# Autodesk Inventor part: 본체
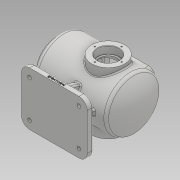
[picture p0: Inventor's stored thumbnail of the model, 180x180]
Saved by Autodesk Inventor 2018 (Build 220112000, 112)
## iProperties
Created: 2021-11
Part Number: 본체
Material: 일반
Document SubType Name: Modeling
Designer: home
Density: 1 g/cm^3
Appearance: 기본값
Author: home
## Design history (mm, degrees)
sketch "스케치1"
  geometry: L1 (-105, 32.5)-(-105, 47.5); L2 (-105, 47.5)-(-95, 47.5); L3 (-95, 47.5)-(-95, 65); L4 (-95, 65)-(80.993, 65); L5 (-105, 0)-(105, 0); L6 (-105, 32.5)-(-80, 32.5); L7 (-80, 32.5)-(-80, 55); L8 (-80, 55)-(76.239, 55); L9 (95, 0)-(105, 0); A1 r 100 centre (5, 0) between (105, 0) and (80.993, 65); A2 r 90 centre (5, 0) between (95, 0) and (76.239, 55); 2 further points
  constraints: 18 end point, 4 perpendicular, 4 point on circle, 3 vertical, 2 centre point, 2 coincident, 2 horizontal, 1 tangent
  dimensions: "d0" = 210 distance of L5.start L5.end; "d1" = 47.5 distance of L5.start L1.end; "d2" = 10 distance of L1.end L2.end; "d3" = 17.5 distance of L2.end L3.end; "d8" = 10 distance of L9.start L5.end; "d9" = 90 distance of L9.start A1.centre; "d11" = 32.5 distance of L1.start L5.start; "d12" = 25 distance of L1.start L6.end; "d13" = 22.5 distance of L6.end L7.end; "d14" = 65 diameter of L6 L5; "d15" = 95 diameter of L2 L5 (derived); "d16" = 110 diameter of L8 L5 (derived); "d17" = 130 diameter of L4 L5 (derived); "d18" = 0 distance from line of point (0, 0) L9; "d19" = 80 distance from line of point (0, 0) L7
revolve "회전1" sketch "스케치1" stored, may be unused: angle "d20" = 90 deg
node "작업 평면1"
sketch "스케치2"
  geometry: L1 (0, 0)-(0, -114); L2 (0, -114)-(-65, -114); L3 (0, -114)-(65, -114); L4 (-65, -114)-(-65, -100); L5 (-65, -100)-(65, -100); L6 (65, -100)-(65, -114)
  constraints: 12 end point, 2 vertical, 1 horizontal, 1 perpendicular, 1 point on line
  dimensions: "d22" = 114 distance of L1.start L1.end; "d23" = 65 distance of L1.end L2.end; "d24" = 65 distance of L1.end L3.end; "d25" = 14 distance of L2.end L4.end; "d26" = 130 distance of L4.end L5.end
extrude "돌출1" join sketch "스케치2" distance "d27" = 160; taper "d28" = 0 deg
node "작업 평면2"
sketch "스케치6"
  geometry: L1 (-105, -47.5)-(-105, 47.5) reference; C1 r 40 at (22, 0); 1 further point
  constraints: 1 centre point
  dimensions: "d61" = 80 diameter of C1; "d62" = 127 distance from line of C1.centre L1; "d63" = 22 distance of C1.centre point (0, 0)
extrude "돌출3" join sketch "스케치6" stored distance "d64" = 160; taper "d65" = 0 deg
sketch "스케치7"
  geometry: C1 r 40 at (0, 0) reference; C2 r 26 at (0, 0); 1 further point
  constraints: 1 centre point, 1 coincident
  dimensions: "d66" = 52 diameter of C2
extrude "돌출4" cut sketch "스케치7" distance "d67" = 18; taper "d68" = 0 deg
sketch "스케치8"
  geometry: C1 r 26 at (0, 0) reference; C2 r 21 at (0, 0); 1 further point
  constraints: 1 centre point, 1 coincident
  dimensions: "d69" = 42 diameter of C2
extrude "돌출5" cut sketch "스케치8" extent not by distance; stored distance "d70" = 18; taper "d71" = 0 deg
node "작업 평면3"
sketch "스케치9"
  geometry: L1 (105, 47.5)-(105, -47.5) reference; L2 (55, 0)-(55, -30); L3 (55, -30)-(-65, -30); L4 (-65, -30)-(-65, 30); L5 (-65, 30)-(55, 30); L6 (55, 30)-(55, 0); 1 further point
  constraints: 10 end point, 2 perpendicular, 1 parallel, 1 point on line
  dimensions: "d74" = 30 distance of L2.start L2.end; "d75" = 120 distance of L2.end L3.end; "d76" = 60 distance of L3.end L4.end; "d77" = 120 distance of L4.end L5.end; "d78" = 50 distance between parallel lines of L2 L1; "d79" = 17.5 distance from line of L1.start L5
extrude "돌출6" join sketch "스케치9" stored distance "d80" = 18; taper "d81" = 0 deg
sketch "스케치11"
  geometry: L1 (-55, 30)-(65, 30) reference; L2 (65, -30)-(-55, -30) reference; L3 (-50, 0)-(60, 0); L4 (-64, 156)-(-64, 106); L5 (5, 0)-(5, 25); L6 (5, 0)-(5, -25); 5 further points
  constraints: 8 end point, 4 coincident, 2 vertical, 1 horizontal, 1 midpoint, 1 point on line
  dimensions: "d93" = 110 distance of L3.start L3.end; "d94" = 50 distance of L4.start L4.end; "d96" = 25 distance of L5.start L5.end; "d97" = 25 distance of L5.start L6.end; "d98" = 30 distance between parallel lines of L2 L3; "d99" = 69 distance between parallel lines of L6 L4; "d100" = 60 distance from line of L1.end L6; "d101" = 186 distance from line of L4.start L2
hole "구멍1" sketch "스케치11" at (5, 25), (60, 0), (5, -25), (-50, 0) diameter "d102" = 3.242; stored, may be unused: countersink angle "d106" = 90 deg, drill point angle "d108" = 118 deg; dims "d103" = 9, "d104" = 4, "d105" = 2, "d107" = 11
sketch "스케치12" dims "d109" = 65
  geometry: C1 r 21 at (0, 0) reference; 6 further points
  constraints: 1 coincident, 1 vertical alignment, 2 other
  dimensions: "d113" = 54.5 distance of point (-22, 0) point (32.5, 0); "d114" = 39.24602 distance of point (-22, 0) point (0, 32.5); "d115" = 39.24602 distance of point (-22, 0) point (0, -32.5); "d116" = 10.5 distance of point (-22, 0) point (-32.5, 0); "d117" = 32.5 distance of point (32.5, 0) C1.centre; "d118" = 32.5 distance of point (0, -32.5) C1.centre; "d119" = 32.5 distance of point (-32.5, 0) C1.centre
hole "구멍2" sketch "스케치12" at (0, 32.5), (-32.5, 0), (0, -32.5), (32.5, 0) diameter "d120" = 3.242; stored, may be unused: countersink angle "d124" = 90 deg, drill point angle "d126" = 118 deg; dims "d121" = 11, "d122" = 4, "d123" = 2, "d125" = 13
sketch "스케치13" dims "d127" = 80
  geometry: 6 further points
  constraints: 1 coincident, 1 vertical alignment, 7 other
  dimensions: "d130" = 360 deg dimension on point (0, 0) point (0, 40) (derived)
hole "구멍3" sketch "스케치13" at (0, 40), (-40, 0), (0, -40), (40, 0) diameter "d132" = 3.242; stored, may be unused: countersink angle "d136" = 90 deg, drill point angle "d138" = 118 deg; dims "d133" = 11, "d134" = 4, "d135" = 2, "d137" = 13
fillet "모깎기1" dims "d139" = 20
fillet "모깎기2" dims "d146" = 10
chamfer "모따기1" distance "d147" = 1; stored, may be unused: second distance "d148" = 2, angle "d149" = 45 deg
fillet "모깎기3" dims "d150" = 15
fillet "모깎기4" dims "d152" = 3
sketch "스케치16"
  geometry: L1 (0, 0)-(120, 0) reference; L2 (-20, 11)-(-20, 0) reference; 2 further points
  constraints: 1 other
  dimensions: "d156" = 5 distance from line of L1 point (60, 5); "d157" = 80 distance from line of point (60, 5) L2
feature "엠보싱1" sketch "스케치16" dims "d0" = 210, "d158" = 0.5, "d159" = 0
fillet "모깎기8" dims "d160" = 3
sketch "스케치23"
  geometry: L1 (-72, -100)-(-55, -100) reference; L2 (-55, -100)-(-41.308, -62.383); L3 (-55, -114)-(65, -114) reference; L4 (65, -100)-(51.308, -62.383); L5 (65, -114)-(65, -103) reference; L6 (-55, -100)-(65, -100); L7 (-41.308, -62.383)-(51.308, -62.383); L8 (-85, -65)-(76.239, -65) reference; 2 further points
  constraints: 8 end point, 1 horizontal, 1 parallel
  dimensions: "d216" = 110 deg angle of L1 L2; "d217" = 160 deg angle of L4 L5; "d219" = 22.53194 distance from line of point (76.239, -65) L4; "d221" = 13.69153 distance from line of L4.end L5
extrude "돌출11" join sketch "스케치23" stored distance "d223" = 14; taper "d224" = 0 deg
node "작업 평면4"
sketch "스케치25"
  geometry: L1 (-7, -100)-(7, -100) reference; L2 (-50, -100)-(-33.809, -55.515); L3 (-62, -100)-(-45, -100) reference; 2 further points
  constraints: 2 end point, 2 other
  dimensions: "d237" = 110 deg angle of L3 L2; "d238" = 53.56248 distance from line of L1.end L2; "d239" = 0 distance from line of L2.start L3
feature "리브8" sketch "스케치25" dims "d240" = 1, "d241" = 14, "d242" = 0, "d243" = 0, "d244" = 1, "d245" = 1
sketch "스케치26"
  geometry: L1 (-55, -7)-(-55, 7) reference; L2 (-45, 0)-(-45, 20); L3 (-45, 20)-(55, 20); L4 (55, 20)-(55, -20); L5 (55, -20)-(-45, -20); L6 (-45, -20)-(-45, 0); 1 further point
  constraints: 10 end point, 2 perpendicular, 1 horizontal, 1 vertical
  dimensions: "d249" = 20 distance of L2.start L2.end; "d250" = 100 distance of L2.end L3.end; "d251" = 40 distance of L3.end L4.end; "d252" = 100 distance of L4.end L5.end; "d253" = 110 distance between parallel lines of L1 L4; "d254" = 20 distance from line of point (0, 0) L3
extrude "돌출12" cut sketch "스케치26" distance "d255" = 30; taper "d256" = 0 deg
fillet "모깎기11" dims "d257" = 5
fillet "모깎기12" dims "d258" = 3
sketch "스케치27"
  geometry: C1 r 9 at (0, -17); C2 r 9 at (120, -17); C3 r 9 at (120, -107); C4 r 9 at (0, -107); A1 r 20 centre (0, -17) between (0, 3) and (-20, -17) reference; A2 r 20 centre (120, -17) between (140, -17) and (120, 3) reference; A3 r 20 centre (120, -107) between (120, -127) and (140, -107) reference; A4 r 20 centre (0, -107) between (-20, -107) and (0, -127) reference; 1 further point
  constraints: 4 centre point, 4 coincident
  dimensions: "d259" = 18 diameter of C1; "d260" = 18 diameter of C2; "d261" = 18 diameter of C3; "d262" = 18 diameter of C4
extrude "돌출13" cut sketch "스케치27" distance "d263" = 2; taper "d264" = 0 deg
sketch "스케치28"
  geometry: C1 r 4.5 at (0, 0); C2 r 4.5 at (0, -90); C3 r 4.5 at (120, -90); C4 r 4.5 at (120, 0); A1 r 20 centre (0, 0) between (0, 20) and (-20, 0) reference; A2 r 20 centre (0, -90) between (-20, -90) and (0, -110) reference; A3 r 20 centre (120, -90) between (120, -110) and (140, -90) reference; A4 r 20 centre (120, 0) between (140, 0) and (120, 20) reference; 1 further point
  constraints: 4 centre point, 4 coincident
  dimensions: "d265" = 9 diameter of C1; "d266" = 9 diameter of C2; "d267" = 9 diameter of C3; "d268" = 9 diameter of C4
extrude "돌출14" cut sketch "스케치28" extent not by distance; stored distance "d269" = 2; taper "d270" = 0 deg
fillet "모깎기13" dims "d271" = 3
fillet "모깎기14" dims "d272" = 3
fillet "모깎기15" dims "d273" = 0.3
fillet "모깎기16" dims "d274" = 3
node "솔리드1"
mirror "미러3"
mirror "미러4"
mirror "미러5"
mirror "미러13"
other parameters: "d59" = 75, "d235" = -73
